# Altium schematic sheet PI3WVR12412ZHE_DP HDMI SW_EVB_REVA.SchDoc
size 386 x 246 mm
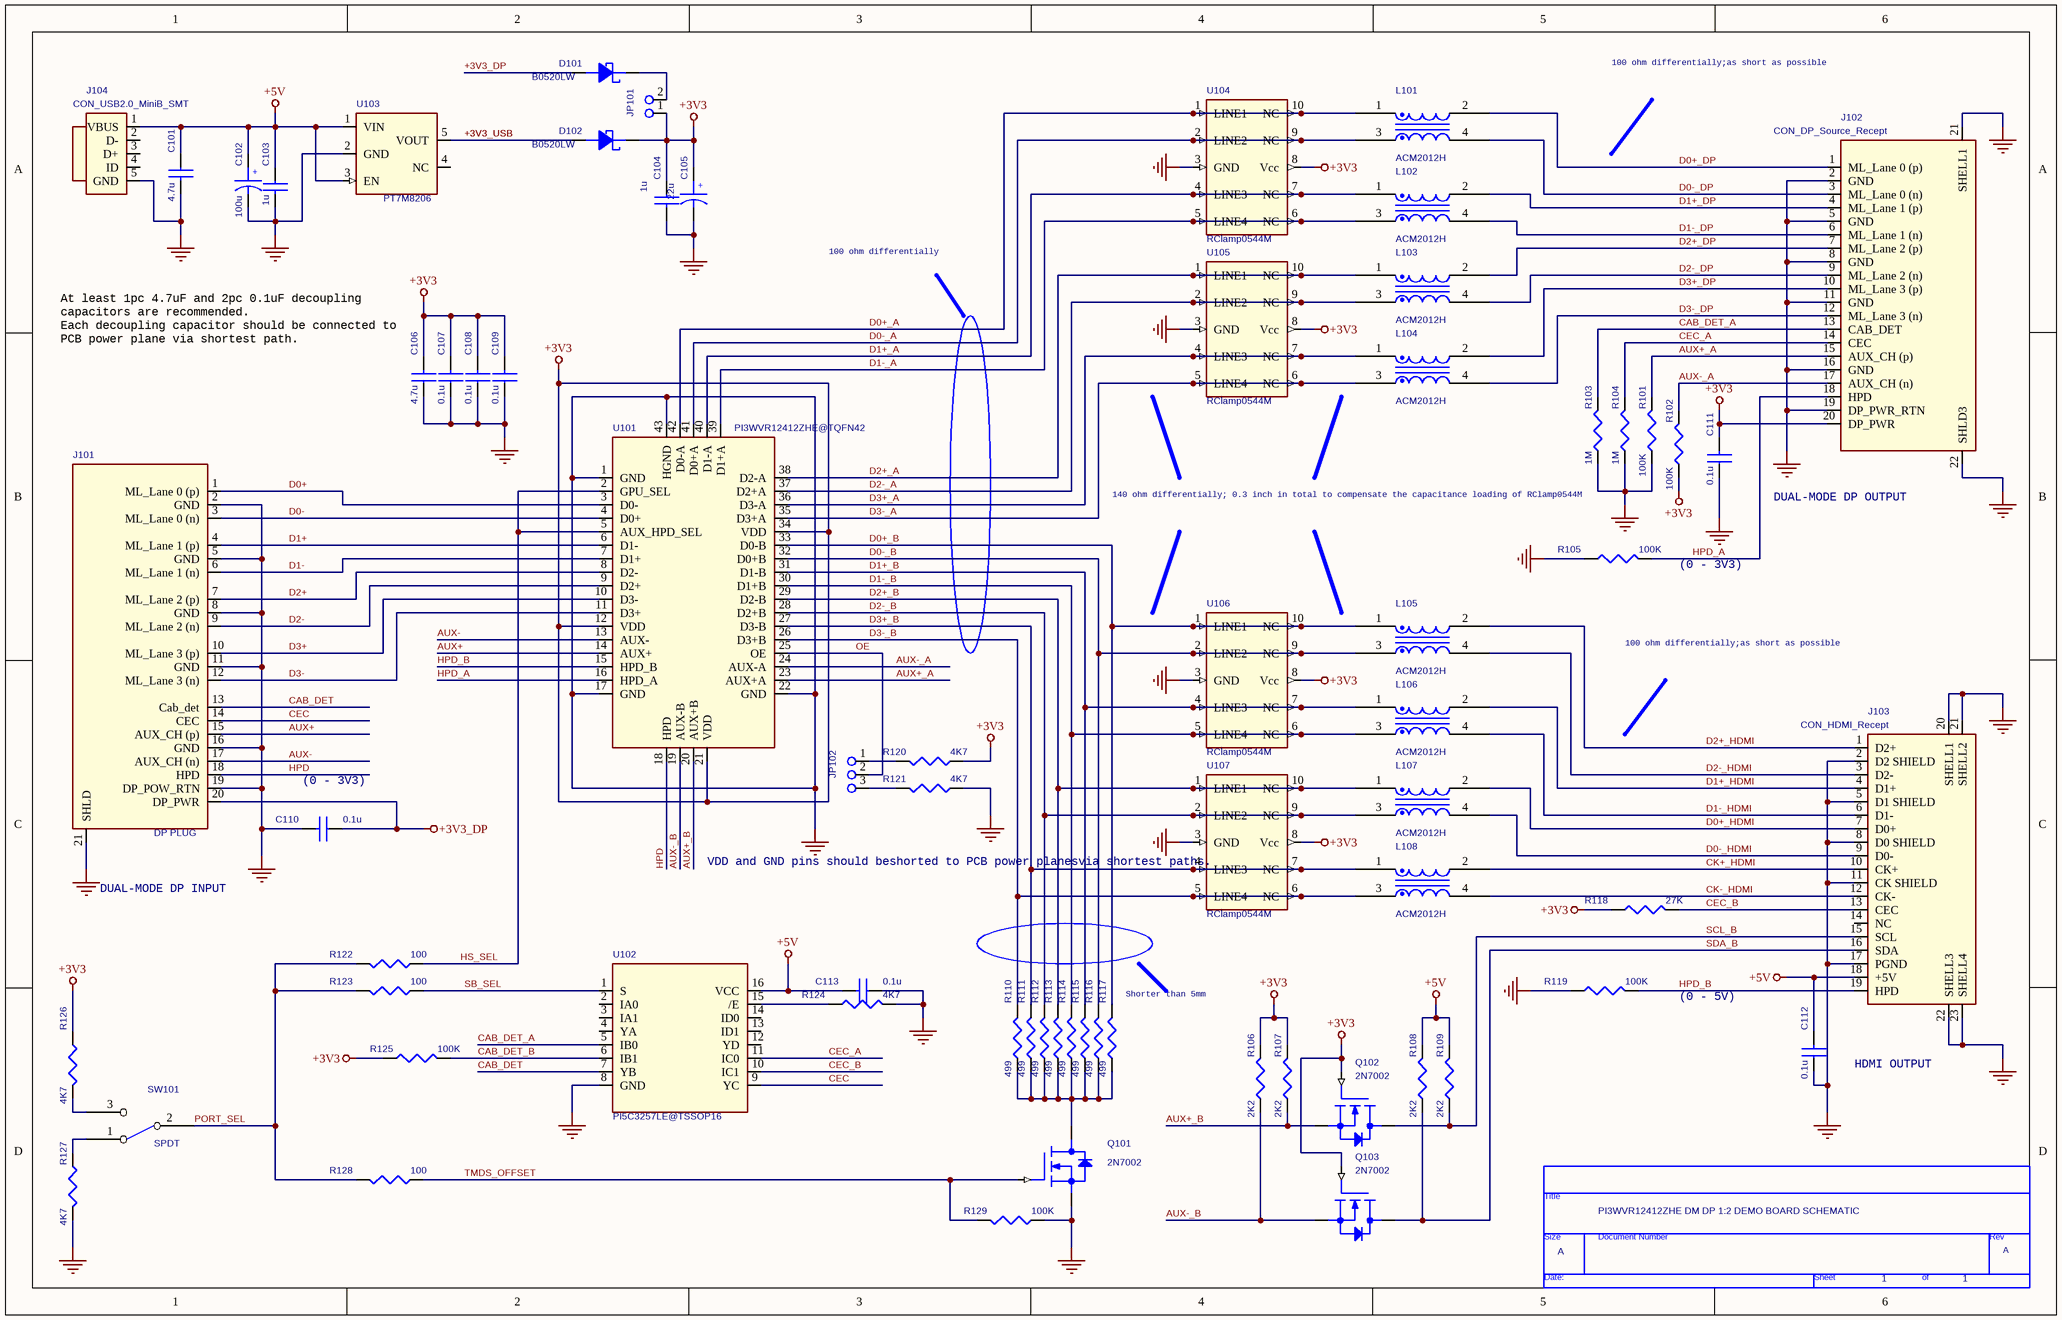
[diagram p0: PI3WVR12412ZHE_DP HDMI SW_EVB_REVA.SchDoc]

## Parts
*  Page Count: 1  Page Size: A  Title: PI3WVR12412ZHE DM DP 1:2 DEMO BOARD SCHEMATIC  (hidden comment: TitleBlock0)  (graphical)
C101  4.7u  [CAP@CC_0805]
C102  100u  [CAP@CT_7343]
C103  1u  [CAP@CC_0805]
C104  1u  [CAP@CC_0805]
C105  22u  [CAP@CT_3528]
C106  4.7u  [CC_0402]
C107  0.1u  [CC_0402]
C108  0.1u  [CC_0402]
C109  0.1u  [CC_0402]
C110  0.1u  [CC_0402]
C111  0.1u  [CC_0402]
C112  0.1u  [CC_0402]
C113  0.1u  [CC_0402]
D101  B0520LW  [D@SOD-123]
D102  B0520LW  [D@SOD-123]
J101  DP PLUG  [CON_DP_PLUG]
J102  CON_DP_Source_Recept  [CON_DP_Recept]
J103  CON_HDMI_Recept  [CON_HDMI_Recept]
J104  CON_USB2.0_MiniB_SMT  [CON_USB2.0_MiniB_SMT]
JP101  2x1 Pin Header  [2x1 Pin Header]  (value not drawn)
JP102  3x1 Pin Header  [3x1 Pin Header]  (value not drawn)
L101  ACM2012H  [ACM2012H]
L102  ACM2012H  [ACM2012H]
L103  ACM2012H  [ACM2012H]
L104  ACM2012H  [ACM2012H]
L105  ACM2012H  [ACM2012H]
L106  ACM2012H  [ACM2012H]
L107  ACM2012H  [ACM2012H]
L108  ACM2012H  [ACM2012H]
Q101  2N7002  [SOT-23-1]
Q102  2N7002  [SOT-23-1]
Q103  2N7002  [SOT-23-1]
R101  100K  [RES@R_0402]
R102  100K  [RES@R_0402]
R103  1M  [RES@R_0402]
R104  1M  [RES@R_0402]
R105  100K  [R_0402]
R106  2K2  [R_0402]
R107  2K2  [R_0402]
R108  2K2  [R_0402]
R109  2K2  [R_0402]
R110  499  [R_0402]
R111  499  [R_0402]
R112  499  [R_0402]
R113  499  [R_0402]
R114  499  [R_0402]
R115  499  [R_0402]
R116  499  [R_0402]
R117  499  [R_0402]
R118  27K  [R_0402]
R119  100K  [R_0402]
R120  4K7  [RES@R_0402]
R121  4K7  [RES@R_0402]
R122  100  [RES@R_0402]
R123  100  [RES@R_0402]
R124  4K7  [R_0402]
R125  100K  [R_0402]
R126  4K7  [R_0402]
R127  4K7  [R_0402]
R128  100  [R_0402]
R129  100K  [R_0402]
SW101  SPDT  [SWSPDT@SWSPDT]
U101  PI3WVR12412ZHE@TQFN42  [TQFN42]
U102  PI5C3257LE@TSSOP16  [TSSOP16]
U103  PT7M8206  [Pow_SOT-23-5]
U104  RClamp0544M  [MSOP10]
U105  RClamp0544M  [MSOP10]
U106  RClamp0544M  [MSOP10]
U107  RClamp0544M  [MSOP10]

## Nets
+3V3: C104.1 C105.1 C106.2 C107.2 C108.2 C109.2 C111.2 D102.2 J102.20(DP_PWR) JP101.1 Q102.1(G) Q103.1(G) R102.1 R106.2 R107.2 R118.1 R120.2 R125.1 R126.2 U101.12(VDD) U101.21(VDD) U101.34(VDD) U104.8(Vcc) U105.8(Vcc) U106.8(Vcc) U107.8(Vcc)
+3V3_DP: C110.1 D101.1 J101.20(DP_PWR)
+5V: C101.1 C102.1 C103.1 C112.2 C113.2 J103.18(+5V) J104.1(VBUS) R108.2 R109.2 U102.16(VCC) U103.1(VIN) U103.3(EN)
GND: C101.2 C102.2 C103.2 C104.2 C105.2 C106.1 C107.1 C108.1 C109.1 C110.2 C111.1 C112.1 C113.1 J101.2(GND) J101.5(GND) J101.8(GND) J101.11(GND) J101.16(GND) J101.19(DP_POW_RTN) J101.21(SHLD) J102.2(GND) J102.5(GND) J102.8(GND) J102.11(GND) J102.16(GND) J102.19(DP_PWR_RTN) J102.21(SHELL1) J102.22(SHLD3) J103.2(D2_SHIELD) J103.5(D1_SHIELD) J103.8(D0_SHIELD) J103.11(CK_SHIELD) J103.17(PGND) J103.20(SHELL1) J103.21(SHELL2) J103.22(SHELL3) J103.23(SHELL4) J104.5(GND) Q101.2(S) R101.1 R103.1 R104.1 R105.1 R119.1 R121.2 R124.2 R127.1 R129.1 U101.1(GND) U101.17(GND) U101.22(GND) U101.43(HGND) U102.8(GND) U103.2(GND) U104.3(GND) U105.3(GND) U106.3(GND) U107.3(GND)
+3V3_USB: D102.1 U103.5(VOUT)
AUX+: J101.15(AUX_CH_(p)) U101.14(AUX+)
AUX+_A: J102.15(AUX_CH_(p)) R101.2 U101.23(AUX+A)
AUX+_B: Q102.2(S) R107.1 U101.20(AUX+B)
AUX-: J101.17(AUX_CH_(n)) U101.13(AUX-)
AUX-_A: J102.17(AUX_CH_(n)) R102.2 U101.24(AUX-A)
AUX-_B: Q103.2(S) R106.1 U101.19(AUX-B)
CAB_DET: J101.13(Cab_det) U102.7(YB)
CAB_DET_A: J102.13(CAB_DET) R103.2 U102.5(IB0)
CAB_DET_B: R125.2 U102.6(IB1)
CEC: J101.14(CEC) U102.9(YC)
CEC_A: J102.14(CEC) R104.2 U102.11(IC0)
CEC_B: J103.13(CEC) R118.2 U102.10(IC1)
CK+_HDMI: J103.10(CK+) L108.2
CK-_HDMI: J103.12(CK-) L108.4
D0+: J101.1(ML_Lane_0_(p)) U101.3(D0-)
D0+_A: L101.1 U101.42(D0-A) U104.1(LINE1) U104.10(NC)
D0+_B: L105.1 R117.2 U101.33(D0-B) U106.1(LINE1) U106.10(NC)
D0+_DP: J102.1(ML_Lane_0_(p)) L101.2
D0+_HDMI: J103.7(D0+) L107.2
D0-: J101.3(ML_Lane_0_(n)) U101.4(D0+)
D0-_A: L101.3 U101.41(D0+A) U104.2(LINE2) U104.9(NC)
D0-_B: L105.3 R116.2 U101.32(D0+B) U106.2(LINE2) U106.9(NC)
D0-_DP: J102.3(ML_Lane_0_(n)) L101.4
D0-_HDMI: J103.9(D0-) L107.4
D1+: J101.4(ML_Lane_1_(p)) U101.6(D1-)
D1+_A: L102.1 U101.40(D1-A) U104.4(LINE3) U104.7(NC)
D1+_B: L106.1 R115.2 U101.31(D1-B) U106.4(LINE3) U106.7(NC)
D1+_DP: J102.4(ML_Lane_1_(p)) L102.2
D1+_HDMI: J103.4(D1+) L106.2
D1-: J101.6(ML_Lane_1_(n)) U101.7(D1+)
D1-_A: L102.3 U101.39(D1+A) U104.5(LINE4) U104.6(NC)
D1-_B: L106.3 R114.2 U101.30(D1+B) U106.5(LINE4) U106.6(NC)
D1-_DP: J102.6(ML_Lane_1_(n)) L102.4
D1-_HDMI: J103.6(D1-) L106.4
D2+: J101.7(ML_Lane_2_(p)) U101.8(D2-)
D2+_A: L103.1 U101.38(D2-A) U105.1(LINE1) U105.10(NC)
D2+_B: L107.1 R113.2 U101.29(D2-B) U107.1(LINE1) U107.10(NC)
D2+_DP: J102.7(ML_Lane_2_(p)) L103.2
D2+_HDMI: J103.1(D2+) L105.2
D2-: J101.9(ML_Lane_2_(n)) U101.9(D2+)
D2-_A: L103.3 U101.37(D2+A) U105.2(LINE2) U105.9(NC)
D2-_B: L107.3 R112.2 U101.28(D2+B) U107.2(LINE2) U107.9(NC)
D2-_DP: J102.9(ML_Lane_2_(n)) L103.4
D2-_HDMI: J103.3(D2-) L105.4
D3+: J101.10(ML_Lane_3_(p)) U101.10(D3-)
D3+_A: L104.1 U101.36(D3-A) U105.4(LINE3) U105.7(NC)
D3+_B: L108.1 R111.2 U101.27(D3-B) U107.4(LINE3) U107.7(NC)
D3+_DP: J102.10(ML_Lane_3_(p)) L104.2
D3-: J101.12(ML_Lane_3_(n)) U101.11(D3+)
D3-_A: L104.3 U101.35(D3+A) U105.5(LINE4) U105.6(NC)
D3-_B: L108.3 R110.2 U101.26(D3+B) U107.5(LINE4) U107.6(NC)
D3-_DP: J102.12(ML_Lane_3_(n)) L104.4
HPD: J101.18(HPD) U101.18(HPD)
HPD_A: J102.18(HPD) R105.2 U101.16(HPD_A)
HPD_B: J103.19(HPD) R119.2 U101.15(HPD_B)
HS_SEL: R122.2 U101.2(GPU_SEL) U101.5(AUX_HPD_SEL)
OE: JP102.2 U101.25(OE)
PORT_SEL: R122.1 R123.1 R128.2 SW101.2(COMMON)
SB_SEL: R123.2 U102.1(S)
SCL_B: J103.15(SCL) Q102.3(D) R109.1
SDA_B: J103.16(SDA) Q103.3(D) R108.1
TMDS_OFFSET: Q101.1(G) R128.1 R129.2
NetD101_2: D101.2 JP101.2
NetJP102_1: JP102.1 R120.1
NetJP102_3: JP102.3 R121.1
NetQ101_3: Q101.3(D) R110.1 R111.1 R112.1 R113.1 R114.1 R115.1 R116.1 R117.1
NetR124_1: R124.1 U102.15(/E)
NetR126_1: R126.1 SW101.3(NO)
NetR127_2: R127.2 SW101.1(NC)

Not connected (* = marked no-connect by the designer): J103 14(NC); J104 2(D-) 3(D+) 4(ID); U102 2(IA0) 3(IA1) 4(YA) 12(YD) 13(ID1) 14(ID0); U103 4(NC)

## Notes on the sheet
- 100 ohm differentially;as short as possible
- 100 ohm differentially
- (near C106) At least 1pc 4.7uF and 2pc 0.1uF decoupling capacitors are recommended.
  Each decoupling capacitor should be connected to PCB power plane via shortest path.
- 140 ohm differentially; 0.3 inch in total to compensate the capacitance loading of RClamp0544M
- DUAL-MODE DP OUTPUT
- (near R105) (0 - 3V3)
- (near C110) (0 - 3V3)
- VDD and GND pins should beshorted to PCB power planesvia shortest paths.
- DUAL-MODE DP INPUT
- Shorter than 5mm
- (0 - 5V)
- HDMI OUTPUT

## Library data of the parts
C101 C103 C104 = CHIP CAP0805
C102 = 100UF 7343_1
C105 = 22UF 3528
C106-C113 = C_0.1u_0402
D101 D102 = SchottkyDiode@SOD-123_1
J101 = CONN_DP_4
J102 = CON_DP_Source_Recept_1
L101-L108 = CMT908
Q101-Q103 = 2N6659
R101-R104 R120-R123 = CHIP RES0402_1
R105-R119 R124-R129 = R_0402
SW101 = SW SPDT_0
U101 = PI3HDMI20412ZHE@TQFN42_0
U102 = PI6C10806LE@TSSOP16_0
U103 = Pow_PT7M8206
U104 U106 = RBO4040/SO_9
U105 U107 = RBO4040/SO_10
